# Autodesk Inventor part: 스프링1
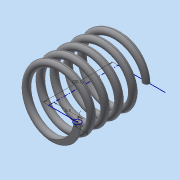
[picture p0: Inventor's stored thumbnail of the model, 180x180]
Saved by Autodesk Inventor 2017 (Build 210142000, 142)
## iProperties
Part Number: 스프링1
Material: 일반
Document SubType Name: Modeling
Designer: MRC
Density: 1 g/cm^3
Appearance: 기본값
Author: MRC
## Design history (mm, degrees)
sketch "스케치1"
  geometry: L1 (0, 0)-(0, 20.5); L2 (0, 0)-(8.5, 0); L3 (0, 20.5)-(14, 20.5); C1 r 1 at (8.5, 0)
  constraints: 6 end point, 2 horizontal, 1 centre point, 1 coincident, 1 vertical
  dimensions: "d0" = 20.5 distance of L1.start L1.end (derived); "d1" = 8.5 distance of L1.start L2.end; "d2" = 2 diameter of C1
feature "코일1" sketch "스케치1" pitch "d3" = 10; turns "d5" = 5; dims "d4" = 20.5 (= d0), "d6" = 0, angle "d7" = 90 deg, angle "d8" = 90 deg, "d9" = 0, "d10" = 0
sketch "스케치2"
  geometry: L1 (20.5, 11)-(0, 11); L2 (0, 11)-(0, -11); L3 (0, -11)-(20.5, -11); L4 (20.5, -11)-(20.5, 11); 2 further points
  constraints: 8 end point, 2 parallel, 1 coincident, 1 horizontal, 1 midpoint, 1 perpendicular
  dimensions: "d11" = 20.5 distance of L2.end L3.end (= d0); "d12" = 22 distance between parallel lines of L3 L1
extrude "돌출1" sketch "스케치2" stored distance "d13" = 50; taper "d14" = 0 deg
node "솔리드1"
